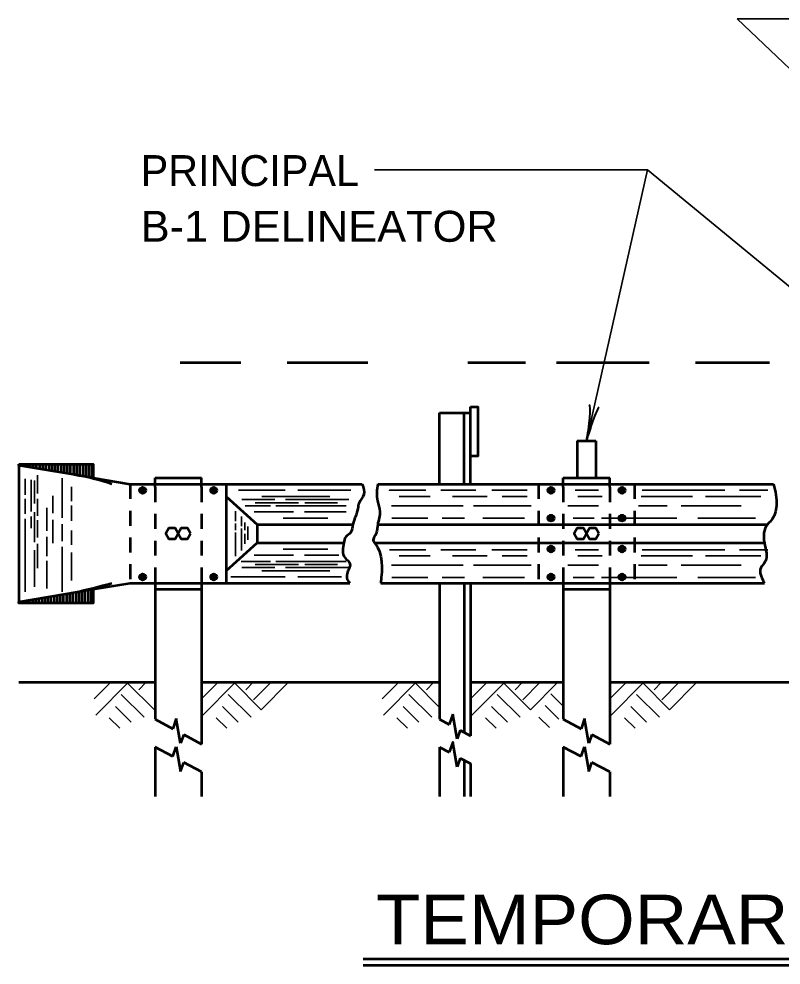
# Model space of a CAD drawing. Extents: x -60 to 620, y -42 to 398.
# Drawn here: x 167 to 228.6, y 75.7 to 152.2 of the extents above; entities that cross this region are included whole.
import ezdxf

# ---------------------------------------------------------------- set-up
doc = ezdxf.new("R2010")
doc.units = 0
doc.header["$LTSCALE"] = 0.8
doc.linetypes.add('SHORT_DASHED', pattern=[2.7, 1.5, -1.2])
doc.layers.add('1', color=7, linetype='Continuous', lineweight=35)

msp = doc.modelspace()

# ---------------------------------------------------------------- hatches: boundary and pattern name
at = {"layer": '1'}
for points in [[(177.2638, 114.0762, 1), (176.7638, 114.0762, 1)], [(183.0138, 114.0762, 1), (182.5138, 114.0762, 1)], [(210.2638, 114.0762, 1), (209.7638, 114.0762, 1)], [(216.0138, 114.0762, 1), (215.5138, 114.0762, 1)], [(210.2638, 111.8262, 1), (209.7638, 111.8262, 1)], [(216.0138, 111.8262, 1), (215.5138, 111.8262, 1)], [(210.2638, 109.3262, 1), (209.7638, 109.3262, 1)], [(216.0138, 109.3262, 1), (215.5138, 109.3262, 1)], [(177.2638, 107.0762, 1), (176.7638, 107.0762, 1)], [(183.0138, 107.0762, 1), (182.5138, 107.0762, 1)], [(210.2638, 107.0762, 1), (209.7638, 107.0762, 1)], [(216.0138, 107.0762, 1), (215.5138, 107.0762, 1)]]:
    msp.add_hatch(color=256, dxfattribs=at).paths.add_polyline_path(points)

# ---------------------------------------------------------------- linework, layer by layer
for p, q in [((258.0138, 120.8262), (225.0642, 152.1655)), ((225.0642, 152.1655), (239.5622, 152.1655)), ((217.8122, 139.9722), (195.7594, 139.9722)), ((217.8122, 139.9722), (212.8888, 118.0762)), ((217.8122, 139.9722), (244.3888, 118.0762)), ((167.5138, 114.9928), (167.5138, 113.7198)), ((168.0138, 114.9095), (168.0138, 112.3714)), ((168.2638, 114.8678), (168.2638, 113.0142)), ((168.5138, 115.3034), (168.5138, 113.8139)), ((170.5138, 115.0682), (170.5138, 111.8383)), ((171.2638, 114.3661), (171.2638, 113.2024)), ((184.7638, 114.0762), (188.5452, 114.0762)), ((189.5557, 114.0762), (193.8382, 114.0762)), ((201.1084, 114.0762), (203.9566, 114.0762)), ((205.2323, 114.0762), (208.0805, 114.0762)), ((211.9671, 114.0762), (213.8658, 114.0762)), ((217.3964, 114.0762), (224.0718, 114.0762)), ((225.2586, 114.0762), (227.5431, 114.0762)), ((167.5138, 113.3905), (167.5138, 112.1676)), ((168.5138, 113.3748), (168.5138, 112.0264)), ((169.7638, 113.6414), (169.7638, 112.2302)), ((185.0416, 113.3262), (187.6925, 113.3262)), ((186.6504, 113.5762), (192.1346, 113.5762)), ((188.5662, 113.3262), (193.6777, 113.3262)), ((197.7558, 113.5762), (200.248, 113.5762)), ((202.0577, 113.5762), (204.8466, 113.5762)), ((206.063, 113.5762), (208.0805, 113.5762)), ((212.1747, 113.5762), (214.1625, 113.5762)), ((217.3074, 113.5762), (221.461, 113.5762)), ((222.4994, 113.5762), (226.9793, 113.5762)), ((169.2638, 112.6692), (169.2638, 110.8034)), ((171.2638, 112.8417), (171.2638, 111.6031)), ((184.5138, 112.4012), (184.5138, 111.5919)), ((185.3136, 112.8262), (187.3346, 112.8262)), ((186.1031, 113.0762), (189.5977, 113.0762)), ((187.7873, 112.8262), (193.4527, 112.8262)), ((190.1241, 113.0762), (192.7662, 113.0762)), ((197.1328, 112.8262), (202.9182, 112.8262)), ((203.7489, 112.8262), (208.4068, 112.8262)), ((211.3737, 112.8262), (213.8658, 112.8262)), ((217.0998, 112.8262), (219.4138, 112.8262)), ((220.5412, 112.8262), (225.3773, 112.8262)), ((167.5138, 111.7756), (167.5138, 105.8802)), ((168.0138, 111.9637), (168.0138, 111.0072)), ((168.2638, 112.3087), (168.2638, 109.8941)), ((168.5138, 111.6502), (168.5138, 110.2703)), ((169.7638, 111.6815), (169.7638, 109.8)), ((185.0138, 111.9512), (185.0138, 111.1667)), ((186.0293, 112.3262), (189.2082, 112.3262)), ((188.3767, 111.8262), (191.9767, 111.8262)), ((190.103, 112.3262), (193.4609, 112.3262)), ((197.1625, 111.8262), (200.07, 111.8262)), ((201.2271, 111.8262), (203.0368, 111.8262)), ((204.5203, 111.8262), (207.8728, 111.8262)), ((211.8187, 111.8262), (213.5098, 111.8262)), ((214.1032, 111.8262), (220.1852, 111.8262)), ((221.8763, 111.8262), (226.5343, 111.8262)), ((170.5138, 111.3366), (170.5138, 109.9724)), ((184.5138, 111.4052), (184.5138, 110.8452)), ((185.0138, 111.0008), (185.0138, 109.2012)), ((185.2638, 111.4778), (185.2638, 110.866)), ((185.5138, 111.146), (185.5138, 110.0675)), ((169.2638, 110.3174), (169.2638, 108.7652)), ((171.2638, 110.8192), (171.2638, 109.6588)), ((184.5138, 110.6586), (184.5138, 108.7512)), ((185.2638, 110.5652), (185.2638, 109.7461)), ((168.5138, 109.7529), (168.5138, 107.793)), ((170.5138, 109.5021), (170.5138, 105.8802)), ((168.2638, 109.2355), (168.2638, 106.2845)), ((171.2638, 109.0474), (171.2638, 106.7844)), ((186.0293, 108.8262), (189.2082, 108.8262)), ((188.3767, 109.3262), (191.9767, 109.3262)), ((190.103, 108.8262), (192.8609, 108.8262)), ((196.9547, 109.2683), (199.892, 109.2683)), ((197.7558, 108.7683), (200.248, 108.7683)), ((201.1084, 109.2683), (203.9566, 109.2683)), ((202.0577, 108.7683), (204.8466, 108.7683)), ((205.2323, 109.2683), (208.0805, 109.2683)), ((206.063, 108.7683), (208.0805, 108.7683)), ((211.9671, 109.2683), (213.8658, 109.2683)), ((212.1747, 108.7683), (214.1625, 108.7683)), ((217.3074, 108.7683), (221.461, 108.7683)), ((217.3964, 109.2683), (224.0718, 109.2683)), ((222.4994, 108.7683), (226.9793, 108.7683)), ((225.2586, 109.2683), (227.5431, 109.2683)), ((169.2638, 108.3732), (169.2638, 106.1467)), ((184.9872, 108.3262), (187.3346, 108.3262)), ((185.0416, 107.8262), (187.6925, 107.8262)), ((186.1031, 108.0762), (189.5977, 108.0762)), ((187.7873, 108.3262), (193.4527, 108.3262)), ((188.5662, 107.8262), (193.6777, 107.8262)), ((190.1241, 108.0762), (192.7662, 108.0762)), ((197.1328, 108.0183), (202.9182, 108.0183)), ((203.7489, 108.0183), (208.4068, 108.0183)), ((211.3737, 108.0183), (213.8658, 108.0183)), ((217.0998, 108.0183), (219.4138, 108.0183)), ((220.5412, 108.0183), (225.3773, 108.0183)), ((184.1347, 107.0762), (188.5452, 107.0762)), ((186.6504, 107.5762), (192.1346, 107.5762)), ((189.5557, 107.0762), (193.0925, 107.0762)), ((197.1625, 107.0183), (200.07, 107.0183)), ((201.2271, 107.0183), (203.0368, 107.0183)), ((204.5203, 107.0183), (207.8728, 107.0183)), ((211.8187, 107.0183), (213.5098, 107.0183)), ((214.1032, 107.0183), (220.1852, 107.0183)), ((221.8763, 107.0183), (226.5343, 107.0183)), ((174.4276, 98.5362), (173.1076, 97.2162)), ((175.8476, 98.5362), (173.2276, 95.9162)), ((175.7476, 98.5362), (178.0138, 96.2699)), ((177.2676, 98.5362), (176.7076, 97.9562)), ((183.0838, 98.5362), (181.7638, 97.2162)), ((184.5038, 98.5362), (181.7638, 95.7962)), ((184.4038, 98.5362), (186.6038, 96.3362)), ((185.9238, 98.5362), (185.3638, 97.9562)), ((187.3638, 98.5362), (185.9838, 97.1562)), ((188.7838, 98.5362), (186.6038, 96.3362)), ((197.6867, 98.5362), (196.3667, 97.2162)), ((199.1067, 98.5362), (196.4867, 95.9162)), ((199.0067, 98.5362), (201.0138, 96.529)), ((200.5267, 98.5362), (199.9667, 97.9562)), ((204.8338, 98.5362), (203.5138, 97.2162)), ((206.2538, 98.5362), (203.6338, 95.9162)), ((206.1538, 98.5362), (208.3538, 96.3362)), ((207.7125, 98.5762), (207.1138, 97.9562)), ((209.1138, 98.5362), (207.7338, 97.1562)), ((210.5338, 98.5362), (208.3538, 96.3362)), ((216.0838, 98.5362), (214.7638, 97.2162)), ((217.5038, 98.5362), (214.8838, 95.9162)), ((217.4038, 98.5362), (219.6038, 96.3362)), ((218.9238, 98.5362), (218.3638, 97.9562)), ((220.3638, 98.5362), (218.9838, 97.1562)), ((221.7838, 98.5362), (219.6038, 96.3362)), ((175.2676, 97.5762), (177.1276, 95.7362)), ((183.9238, 97.5762), (185.7838, 95.7362)), ((198.5267, 97.5762), (200.3867, 95.7362)), ((205.6738, 97.5762), (207.5338, 95.7362)), ((210.0138, 97.6362), (211.0138, 96.6362)), ((216.9238, 97.5762), (218.7838, 95.7362)), ((174.8076, 96.6162), (176.0876, 95.3362)), ((183.4638, 96.6162), (184.7438, 95.3362)), ((198.0667, 96.6162), (199.3467, 95.3362)), ((205.2138, 96.6162), (206.4938, 95.3362)), ((209.5538, 96.6762), (210.6559, 95.5741)), ((216.4638, 96.6162), (217.7438, 95.3362)), ((174.3076, 95.6962), (175.1676, 94.8562)), ((182.9638, 95.6962), (183.8238, 94.8562)), ((197.5667, 95.6962), (198.4267, 94.8562)), ((204.7138, 95.6962), (205.5738, 94.8562)), ((209.0338, 95.7562), (209.8938, 94.8962)), ((215.9638, 95.6962), (216.8238, 94.8562))]:
    msp.add_line(p, q, dxfattribs=at)
at = {"layer": '1', "lineweight": 53}
for p, q in [((180.051, 124.3998), (184.9572, 124.3998)), ((188.7072, 124.3998), (195.2157, 124.3998)), ((203.3101, 124.3998), (207.9572, 124.3998)), ((210.4572, 124.3998), (217.9572, 124.3998)), ((221.7072, 124.3998), (227.6907, 124.3998)), ((203.5138, 114.5762), (203.5138, 120.8262)), ((201.0138, 114.5762), (201.0138, 120.3262)), ((201.0138, 120.3262), (203.5138, 120.3262)), ((203.0138, 114.5762), (203.0138, 120.3262)), ((212.1388, 118.0762), (212.1388, 115.0762)), ((212.1388, 118.0762), (213.6388, 118.0762)), ((213.6388, 118.0762), (213.6388, 115.0762)), ((167.0138, 116.2012), (167.0138, 104.9512)), ((167.196, 116.0458), (167.196, 116.2012)), ((167.446, 116.0042), (167.446, 116.2012)), ((167.696, 115.9625), (167.696, 116.2012)), ((167.946, 115.9208), (167.946, 116.2012)), ((168.196, 115.8792), (168.196, 116.2012)), ((168.446, 115.8375), (168.446, 116.2012)), ((168.696, 115.7958), (168.696, 116.2012)), ((168.946, 115.7542), (168.946, 116.2012)), ((169.196, 115.7125), (169.196, 116.2012)), ((169.446, 115.6708), (169.446, 116.2012)), ((169.696, 115.6292), (169.696, 116.2012)), ((169.946, 115.5875), (169.946, 116.2012)), ((170.196, 115.5458), (170.196, 116.2012)), ((170.446, 115.5042), (170.446, 116.2012)), ((170.696, 115.4625), (170.696, 116.2012)), ((170.946, 115.4208), (170.946, 116.2012)), ((171.196, 115.3792), (171.196, 116.2012)), ((171.446, 115.3375), (171.446, 116.2012)), ((171.696, 115.2958), (171.696, 116.2012)), ((171.946, 115.2542), (171.946, 116.2012)), ((172.196, 115.2125), (172.196, 116.2012)), ((172.446, 115.1708), (172.446, 116.2012)), ((172.696, 115.1292), (172.696, 116.2012)), ((172.946, 115.0875), (172.946, 116.2012)), ((173.0138, 115.0763), (176.0138, 114.5762)), ((178.0138, 114.3262), (178.0138, 115.0762)), ((178.0138, 115.0762), (181.7638, 115.0762)), ((181.7638, 114.3262), (181.7638, 115.0762)), ((211.0138, 114.3262), (211.0138, 115.0762)), ((211.0138, 115.0762), (214.7638, 115.0762)), ((214.7638, 114.3262), (214.7638, 115.0762)), ((176.0138, 114.5762), (194.7638, 114.5762)), ((183.7638, 114.5762), (183.7638, 106.5762)), ((196.0138, 114.5762), (228.0138, 114.5762)), ((183.7638, 113.5762), (186.2638, 111.3262)), ((186.2638, 111.3262), (186.2638, 109.8262)), ((186.2638, 111.3262), (194.0138, 111.3262)), ((196.0138, 111.3262), (227.5138, 111.3262)), ((183.7638, 107.5762), (186.2638, 109.8262)), ((186.2638, 109.8262), (193.2638, 109.8262)), ((195.7638, 109.8262), (227.2638, 109.8262)), ((173.0138, 106.0762), (176.0138, 106.5762)), ((178.0138, 106.8262), (178.0138, 95.5762)), ((181.7638, 106.8262), (181.7638, 93.5762)), ((196.2638, 106.5762), (227.2638, 106.5762)), ((201.0138, 106.5762), (201.0138, 95.5762)), ((203.0138, 106.5762), (203.0138, 94.5095)), ((203.5138, 106.5762), (203.5138, 94.2428)), ((211.0138, 106.8262), (211.0138, 95.5762)), ((214.7638, 106.8262), (214.7638, 93.5762)), ((167.0138, 105.0762), (173.0138, 106.0761)), ((169.6302, 104.9512), (169.6302, 105.5122)), ((169.8802, 104.9512), (169.8802, 105.5538)), ((170.1302, 104.9512), (170.1302, 105.5955)), ((170.3802, 104.9512), (170.3802, 105.6372)), ((170.6302, 104.9512), (170.6302, 105.6788)), ((170.8802, 104.9512), (170.8802, 105.7205)), ((171.1302, 104.9512), (171.1302, 105.7622)), ((171.3802, 104.9512), (171.3802, 105.8038)), ((171.6302, 104.9512), (171.6302, 105.8455)), ((171.8802, 104.9512), (171.8802, 105.8872)), ((172.1302, 104.9512), (172.1302, 105.9288)), ((172.3802, 104.9512), (172.3802, 105.9705)), ((172.6302, 104.9512), (172.6302, 106.0122)), ((172.8802, 104.9512), (172.8802, 106.0538)), ((178.0138, 106.0762), (181.7638, 106.0762)), ((211.0138, 106.0762), (214.7638, 106.0762)), ((167.1302, 104.9512), (167.1302, 105.0956)), ((167.3802, 104.9512), (167.3802, 105.1372)), ((167.6302, 104.9512), (167.6302, 105.1789)), ((167.8802, 104.9512), (167.8802, 105.2206)), ((168.1302, 104.9512), (168.1302, 105.2622)), ((168.3802, 104.9512), (168.3802, 105.3038)), ((168.6302, 104.9512), (168.6302, 105.3455)), ((168.8802, 104.9512), (168.8802, 105.3872)), ((169.1302, 104.9512), (169.1302, 105.4288)), ((169.3802, 104.9512), (169.3802, 105.4705)), ((167.0138, 98.5762), (178.0138, 98.5762)), ((181.7638, 98.5762), (201.0138, 98.5762)), ((203.5138, 98.5762), (211.0138, 98.5762)), ((214.7638, 98.5762), (233.7638, 98.5762)), ((178.0138, 95.5762), (179.4476, 94.8114)), ((179.7334, 95.6307), (179.4476, 94.8114)), ((180.0848, 93.638), (179.7334, 95.6307)), ((201.0138, 95.5762), (201.7889, 95.1628)), ((202.0747, 95.9821), (201.7889, 95.1628)), ((202.4262, 93.9893), (202.0747, 95.9821)), ((211.0138, 95.5762), (212.4476, 94.8114)), ((212.7334, 95.6307), (212.4476, 94.8114)), ((213.0848, 93.638), (212.7334, 95.6307)), ((180.33, 94.3408), (180.0848, 93.638)), ((180.33, 94.3408), (181.7638, 93.5762)), ((202.6713, 94.6922), (202.4262, 93.9893)), ((202.6713, 94.6922), (203.5138, 94.2428)), ((213.33, 94.3408), (213.0848, 93.638)), ((213.33, 94.3408), (214.7638, 93.5762)), ((179.4477, 92.5615), (178.0138, 93.3262)), ((178.0138, 93.3262), (178.0138, 89.3262)), ((179.4477, 92.5615), (179.7202, 93.3427)), ((179.7202, 93.3427), (180.0716, 91.35)), ((201.0138, 93.3262), (201.0138, 89.3262)), ((201.0138, 93.3262), (201.7889, 92.9128)), ((212.4477, 92.5615), (211.0138, 93.3262)), ((211.0138, 93.3262), (211.0138, 89.3262)), ((212.4477, 92.5615), (212.7202, 93.3427)), ((212.7202, 93.3427), (213.0716, 91.35)), ((180.0716, 91.35), (180.3301, 92.0909)), ((181.7638, 91.3262), (180.3301, 92.0909)), ((202.6713, 92.4422), (202.4262, 91.7393)), ((202.6713, 92.4422), (203.5138, 91.9928)), ((203.0138, 92.2595), (203.0138, 89.3262)), ((203.5138, 91.9928), (203.5138, 89.3262)), ((213.0716, 91.35), (213.3301, 92.0909)), ((214.7638, 91.3262), (213.3301, 92.0909)), ((181.7638, 91.3262), (181.7638, 89.3262)), ((214.7638, 91.3262), (214.7638, 89.3262)), ((194.8453, 76.2125), (299.5077, 76.2125)), ((194.8453, 75.7125), (299.5077, 75.7125))]:
    msp.add_line(p, q, dxfattribs=at)
at = {"layer": '1', "linetype": 'SHORT_DASHED', "lineweight": 53}
for p, q in [((176.0138, 114.5762), (176.0138, 106.5762)), ((178.0138, 114.3262), (178.0138, 106.8262)), ((181.7638, 114.3262), (181.7638, 106.8262)), ((209.0138, 114.5762), (209.0138, 106.5762)), ((211.0138, 114.3262), (211.0138, 106.8262)), ((214.7638, 114.3262), (214.7638, 106.8262)), ((216.7638, 114.5762), (216.7638, 106.5762))]:
    msp.add_line(p, q, dxfattribs=at)
at = {"layer": '1', "lineweight": 53}
for points in [[(203.5138, 120.8262), (204.1138, 120.8262), (204.1138, 116.8262), (203.5138, 116.8262)], [(176.0138, 106.5762), (178.0138, 106.5762), (181.7638, 106.5762), (193.7638, 106.5762)], [(173.0138, 106.0762), (173.0138, 104.9512), (167.0138, 104.9512), (167.0138, 105.0762)], [(202.4262, 91.7393), (202.0747, 93.7321), (201.7889, 92.9128)]]:
    msp.add_lwpolyline(points, dxfattribs=at)
for points in [[(167.0138, 116.2012), (173.0138, 116.2012), (173.0138, 115.0762), (167.0138, 116.0762)], [(179.8888, 110.5762), (179.6388, 111.0092), (179.1388, 111.0092), (178.8888, 110.5762), (179.1388, 110.1432), (179.6388, 110.1432)], [(180.8888, 110.5762), (180.6388, 111.0092), (180.1388, 111.0092), (179.8888, 110.5762), (180.1388, 110.1432), (180.6388, 110.1432)], [(212.8888, 110.5762), (212.6388, 111.0092), (212.1388, 111.0092), (211.8888, 110.5762), (212.1388, 110.1432), (212.6388, 110.1432)], [(213.8888, 110.5762), (213.6388, 111.0092), (213.1388, 111.0092), (212.8888, 110.5762), (213.1388, 110.1432), (213.6388, 110.1432)]]:
    msp.add_lwpolyline(points, close=True, dxfattribs=at)
at = {"layer": '1'}
msp.add_lwpolyline([(197.0142, 114.0762), (196.9547, 114.0762), (199.892, 114.0762)], dxfattribs=at)
at = {"layer": '1', "lineweight": 53}
for centre in [(177.0138, 114.0762), (182.7638, 114.0762), (210.0138, 114.0762), (215.7638, 114.0762), (210.0138, 111.8262), (215.7638, 111.8262), (210.0138, 109.3262), (215.7638, 109.3262), (177.0138, 107.0762), (182.7638, 107.0762), (210.0138, 107.0762), (215.7638, 107.0762)]:
    msp.add_circle(centre, 0.25, dxfattribs=at)
for centre, radius, start, end in [((168.3349, 96.2354), 19.3536, 71.3815, 80.54601), ((158.5237, 164.1618), 59.7645, 282.55378, 285.51871)]:
    msp.add_arc(centre, radius, start, end, dxfattribs=at)
at = {"layer": '1', "lineweight": 40}
for centre, major_axis, ratio, start_param, end_param in [((212.8586, 119.2014), (-0.2394, -1.7765), 0.122415, 0.8963533, 3.1415927), ((212.8586, 119.2014), (-0.2394, -1.7765), 0.122415, 0.8963533, 3.1415927), ((213.3411, 119.123), (-0.5567, -1.6751), 0.07063, 3.1407148, 5.41811), ((213.3411, 119.123), (-0.5567, -1.6751), 0.07063, 3.1407148, 5.41811)]:
    msp.add_ellipse(centre, major_axis=major_axis, ratio=ratio, start_param=start_param, end_param=end_param, dxfattribs=at)
at = {"layer": '1', "lineweight": 53}
for points in [[(194.7638, 114.5762), (194.8895, 113.7309), (194.5012, 113.0512), (194.4042, 112.6143), (194.2343, 112.0075), (194.0138, 111.3262), (193.8218, 110.6482), (193.4336, 110.3083), (193.2638, 109.8262), (193.3607, 108.6334), (193.7732, 108.148), (193.6034, 107.5412), (193.5549, 106.8615), (193.7638, 106.5762)], [(196.0138, 114.5762), (195.9863, 113.2265), (196.1889, 112.3653), (196.0138, 111.3262), (195.885, 110.5922), (195.6825, 109.9338), (195.7638, 109.8262), (196.2638, 106.5762)], [(228.0138, 114.5762), (228.2455, 112.8212), (227.7897, 111.6054), (227.5138, 111.3262), (227.2638, 109.8262), (227.3339, 108.3127), (226.9794, 107.8061), (227.2638, 106.5762)]]:
    msp.add_spline(points, degree=3, dxfattribs=at)

# ---------------------------------------------------------------- texts
at = {"layer": '1'}
msp.add_text('PRINCIPAL', height=2.5, dxfattribs=at).set_placement((176.8532, 138.6583))
for s, height, width, p in [('B-1 DELINEATOR', 2.5, 1.05, (176.8532, 134.1583)), ('TEMPORARY GUARDRAIL BARRIER', 4, 1.1, (195.8659, 77.3969))]:
    msp.add_text(s, height=height, dxfattribs=dict(at, width=width)).set_placement(p)

doc.saveas('drawing.dxf')
